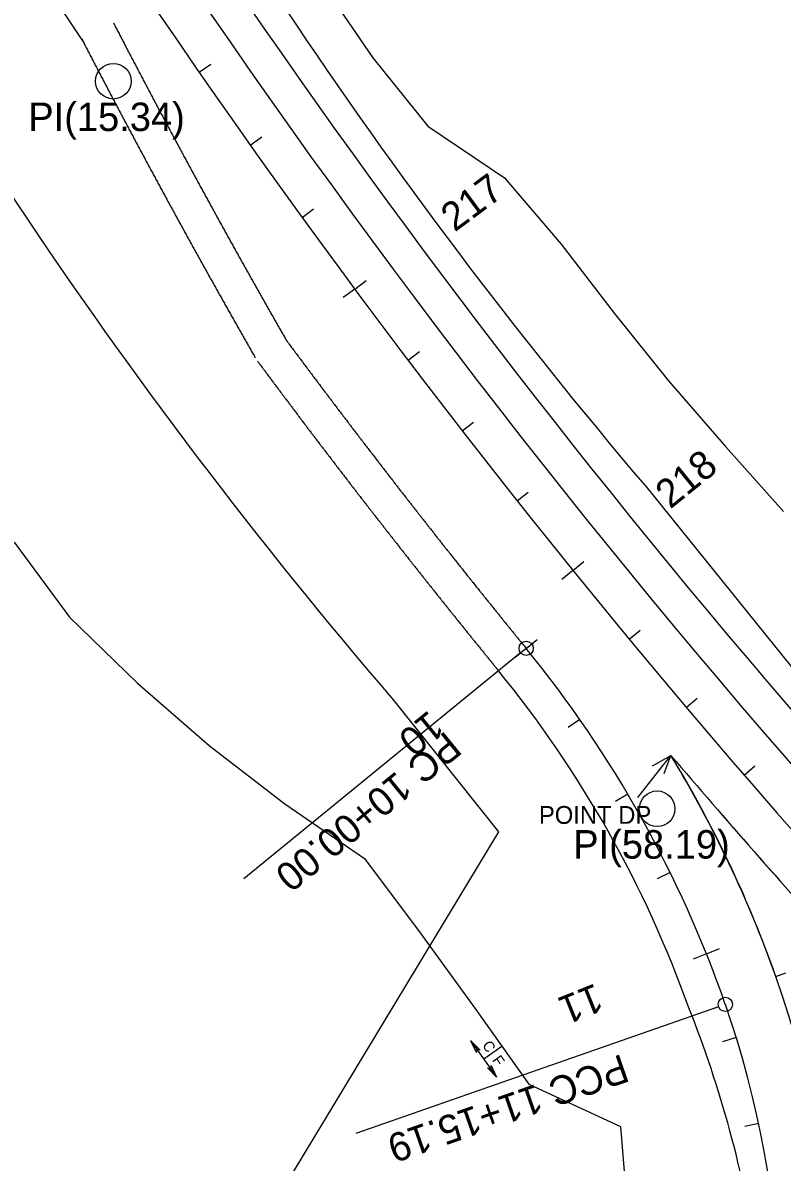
# Model space of a CAD drawing. Extents: x 2717836 to 2719883, y 337327 to 339806.
# Drawn here: x 2718764.3 to 2718977.8, y 338088.2 to 338408.2 of the extents above; entities that cross this region are included whole.
import ezdxf

# ---------------------------------------------------------------- set-up
doc = ezdxf.new("R2010")
doc.units = 0
for name, color, linetype in [('Level 1', 7, 'Continuous'), ('Level 2', 7, 'Continuous'), ('Level 22', 7, 'Continuous'), ('Level 23', 7, 'Continuous'), ('Level 3', 7, 'Continuous'), ('Level 31', 7, 'Continuous'), ('Level 52', 7, 'Continuous'), ('Level 6', 7, 'Continuous'), ('Level 62', 7, 'Continuous'), ('Level 8', 7, 'Continuous')]:
    doc.layers.add(name, color=color, linetype=linetype)

msp = doc.modelspace()

# ---------------------------------------------------------------- linework, layer by layer
at = {"layer": 'Level 1'}
for centre, radius, start, end in [((2720744.45, 339734.24), 2350, 206.79977, 222.16044), ((2718650.19, 338023.77), 330, 19.2398, 39.2398), ((2718697.4, 338040.25), 280, 343.9547, 19.2398)]:
    msp.add_arc(centre, radius, start, end, dxfattribs=at)
at = {"layer": 'Level 2'}
msp.add_arc((2718692.92, 338040.11), 300.27, 344.2175, 19.5026, dxfattribs=at)
at = {"layer": 'Level 22'}
for p, q in [((2718848.86, 338418.64), (2718862.69, 338398.35)), ((2718862.69, 338398.35), (2718878.13, 338379.22)), ((2718878.13, 338379.22), (2718899.73, 338364.7)), ((2718899.73, 338364.7), (2718915.62, 338346.08)), ((2718915.62, 338346.08), (2718930.49, 338326.7)), ((2718930.49, 338326.7), (2718945.81, 338307.67)), ((2718945.81, 338307.67), (2718961.78, 338289.18)), ((2718961.78, 338289.18), (2718978.1, 338271)), ((2718761.89, 338262.37), (2718777.48, 338241.23)), ((2718777.48, 338241.23), (2718796.55, 338222.77)), ((2718796.55, 338222.77), (2718816.65, 338205.23)), ((2718816.65, 338205.23), (2718837.98, 338188.83)), ((2718837.98, 338188.83), (2718860.37, 338173.48)), ((2718860.37, 338173.48), (2718875.97, 338152.58)), ((2718875.97, 338152.58), (2718891.4, 338131.5)), ((2718891.4, 338131.5), (2718898.97, 338120.79)), ((2718898.97, 338120.79), (2718906.54, 338110.09)), ((2718906.54, 338110.09), (2718932.31, 338098.2)), ((2718932.31, 338098.2), (2718934.9, 338066.65))]:
    msp.add_line(p, q, dxfattribs=at)
at = {"layer": 'Level 23'}
for p, q in [((2718939.3, 338278.13), (2718990.26, 338215.01)), ((2718868.5, 338217.98), (2718898.01, 338180.98)), ((2718898.01, 338180.98), (2718493, 337510.9))]:
    msp.add_line(p, q, dxfattribs=at)
for centre, start, end in [((2720030.05, 339206.57), 206.96023, 220.40436), ((2719954.56, 339151.91), 206.65897, 220.69325)]:
    msp.add_arc(centre, 1432.39, start, end, dxfattribs=at)
at = {"layer": 'Level 3'}
msp.add_line((2718975.96, 338140.35), (2718978.77, 338141.36), dxfattribs=at)
for centre, radius, start, end in [((2720744.45, 339734.24), 2338, 206.79977, 222.16044), ((2718650.19, 338023.77), 330, 19.2398, 39.2398), ((2718650.19, 338023.77), 330, 19.2398, 39.2398), ((2718662.07, 338029.42), 332.92, 19.8259, 31.3168), ((2720759.57, 339747.51), 2382.12, 220.43651, 222.14825), ((2718640.38, 338021.68), 355.94, 19.4749, 19.8142), ((2718697.4, 338040.25), 280, 343.9547, 19.2398), ((2718697.4, 338040.25), 280, 343.9547, 19.2398)]:
    msp.add_arc(centre, radius, start, end, dxfattribs=at)
for points in [[(2718789.79, 338408.22), (2718790.1, 338407.61), (2718790.41, 338407.01), (2718790.73, 338406.4), (2718791.04, 338405.79), (2718791.36, 338405.18), (2718791.67, 338404.58), (2718791.99, 338403.97), (2718792.31, 338403.36), (2718792.62, 338402.76), (2718792.94, 338402.15), (2718793.25, 338401.54), (2718793.57, 338400.93), (2718793.88, 338400.33), (2718794.2, 338399.72), (2718794.52, 338399.11), (2718794.84, 338398.51), (2718795.16, 338397.9), (2718795.47, 338397.3), (2718795.79, 338396.69), (2718796.1, 338396.09), (2718796.43, 338395.48), (2718796.74, 338394.88), (2718797.06, 338394.27), (2718797.38, 338393.66), (2718797.7, 338393.06), (2718798.02, 338392.45), (2718798.33, 338391.85), (2718798.66, 338391.24), (2718798.97, 338390.64), (2718799.3, 338390.03), (2718799.62, 338389.42), (2718799.93, 338388.82), (2718800.26, 338388.21), (2718800.57, 338387.61), (2718800.9, 338387), (2718801.21, 338386.4), (2718801.54, 338385.79), (2718801.86, 338385.18), (2718802.18, 338384.58), (2718802.5, 338383.97), (2718802.82, 338383.37), (2718803.15, 338382.77), (2718803.47, 338382.17), (2718803.79, 338381.56), (2718804.12, 338380.95), (2718804.44, 338380.35), (2718804.76, 338379.74), (2718805.08, 338379.14), (2718805.41, 338378.54), (2718805.73, 338377.94), (2718806.05, 338377.33), (2718806.38, 338376.72), (2718806.7, 338376.12), (2718807.03, 338375.52), (2718807.35, 338374.92), (2718807.67, 338374.31), (2718808, 338373.71), (2718808.32, 338373.1), (2718808.64, 338372.51), (2718808.97, 338371.9), (2718809.3, 338371.29), (2718809.62, 338370.69), (2718809.95, 338370.09), (2718810.27, 338369.49), (2718810.6, 338368.88), (2718810.93, 338368.29), (2718811.26, 338367.68), (2718811.58, 338367.07), (2718811.91, 338366.48), (2718812.24, 338365.87), (2718812.56, 338365.27), (2718812.89, 338364.67), (2718813.22, 338364.07), (2718813.55, 338363.46)], [(2718813.55, 338363.46), (2718813.88, 338362.86), (2718814.2, 338362.26), (2718814.53, 338361.65), (2718814.86, 338361.06), (2718815.19, 338360.45), (2718815.52, 338359.85), (2718815.85, 338359.25), (2718816.18, 338358.64), (2718816.51, 338358.05), (2718816.84, 338357.44), (2718817.16, 338356.85), (2718817.5, 338356.24), (2718817.82, 338355.64), (2718818.16, 338355.04), (2718818.49, 338354.44), (2718818.82, 338353.84), (2718819.15, 338353.23), (2718819.48, 338352.64), (2718819.81, 338352.03), (2718820.14, 338351.44), (2718820.48, 338350.83), (2718820.81, 338350.24), (2718821.14, 338349.63), (2718821.48, 338349.03), (2718821.8, 338348.43), (2718822.14, 338347.83), (2718822.47, 338347.24), (2718822.8, 338346.63), (2718823.13, 338346.04), (2718823.47, 338345.43), (2718823.81, 338344.83), (2718824.14, 338344.23), (2718824.47, 338343.63), (2718824.81, 338343.04), (2718825.14, 338342.43), (2718825.47, 338341.84), (2718825.81, 338341.24), (2718826.15, 338340.63), (2718826.48, 338340.04), (2718826.82, 338339.44), (2718827.15, 338338.84), (2718827.49, 338338.24), (2718827.82, 338337.65), (2718828.16, 338337.04), (2718828.5, 338336.44), (2718828.83, 338335.85), (2718829.17, 338335.24), (2718829.5, 338334.65), (2718829.84, 338334.05), (2718830.18, 338333.45), (2718830.52, 338332.85), (2718830.86, 338332.25), (2718831.19, 338331.66), (2718831.53, 338331.06), (2718831.87, 338330.46), (2718832.21, 338329.86), (2718832.54, 338329.27), (2718832.89, 338328.67), (2718833.22, 338328.07), (2718833.56, 338327.47), (2718833.9, 338326.87), (2718834.24, 338326.28), (2718834.58, 338325.68), (2718834.92, 338325.09), (2718835.26, 338324.49), (2718835.6, 338323.89), (2718835.94, 338323.29), (2718836.28, 338322.69), (2718836.62, 338322.1), (2718836.97, 338321.5), (2718837.3, 338320.91), (2718837.65, 338320.31), (2718838.33, 338319.12)], [(2718838.33, 338319.12), (2718838.77, 338318.52), (2718839.22, 338317.92), (2718839.66, 338317.33), (2718840.1, 338316.73), (2718840.54, 338316.14), (2718840.99, 338315.54), (2718841.43, 338314.95), (2718841.87, 338314.36), (2718842.32, 338313.76), (2718842.76, 338313.17), (2718843.21, 338312.57), (2718843.65, 338311.98), (2718844.09, 338311.39), (2718844.54, 338310.79), (2718844.98, 338310.2), (2718845.43, 338309.6), (2718845.87, 338309.01), (2718846.32, 338308.42), (2718846.76, 338307.83), (2718847.21, 338307.24), (2718847.66, 338306.64), (2718848.1, 338306.05), (2718848.55, 338305.45), (2718848.99, 338304.86), (2718849.44, 338304.28), (2718849.89, 338303.68), (2718850.33, 338303.09), (2718850.78, 338302.49), (2718851.23, 338301.91), (2718851.68, 338301.31), (2718852.12, 338300.72), (2718852.57, 338300.13), (2718853.02, 338299.54), (2718853.47, 338298.95), (2718853.92, 338298.36), (2718854.37, 338297.77), (2718854.82, 338297.17), (2718855.26, 338296.59), (2718855.71, 338296), (2718856.16, 338295.4), (2718856.61, 338294.82), (2718857.06, 338294.22), (2718857.51, 338293.64), (2718857.96, 338293.05), (2718858.41, 338292.46), (2718858.86, 338291.87), (2718859.32, 338291.28), (2718859.76, 338290.69), (2718860.22, 338290.1), (2718860.67, 338289.51), (2718861.12, 338288.93), (2718861.57, 338288.34), (2718862.02, 338287.75), (2718862.48, 338287.16), (2718862.93, 338286.57), (2718863.38, 338285.99), (2718863.83, 338285.4), (2718864.28, 338284.81), (2718864.74, 338284.22), (2718865.19, 338283.64), (2718865.65, 338283.05), (2718866.1, 338282.46), (2718866.55, 338281.88), (2718867.01, 338281.29), (2718867.46, 338280.7), (2718867.91, 338280.11), (2718868.37, 338279.53), (2718868.82, 338278.95), (2718869.28, 338278.36), (2718869.73, 338277.77), (2718870.19, 338277.18), (2718870.64, 338276.6), (2718871.1, 338276.01), (2718871.55, 338275.43)], [(2718871.55, 338275.43), (2718872.01, 338274.85), (2718872.47, 338274.26), (2718872.92, 338273.68), (2718873.38, 338273.09), (2718873.83, 338272.51), (2718874.29, 338271.92), (2718874.75, 338271.34), (2718875.2, 338270.76), (2718875.66, 338270.17), (2718876.12, 338269.59), (2718876.58, 338269), (2718877.03, 338268.42), (2718877.49, 338267.84), (2718877.95, 338267.25), (2718878.41, 338266.67), (2718878.87, 338266.08), (2718879.33, 338265.5), (2718879.79, 338264.92), (2718880.25, 338264.34), (2718880.7, 338263.76), (2718881.17, 338263.17), (2718881.62, 338262.59), (2718882.09, 338262.01), (2718882.54, 338261.43), (2718883, 338260.85), (2718883.46, 338260.26), (2718883.92, 338259.69), (2718884.39, 338259.1), (2718884.85, 338258.52), (2718885.31, 338257.94), (2718885.77, 338257.36), (2718886.23, 338256.78), (2718886.69, 338256.2), (2718887.15, 338255.62), (2718887.62, 338255.04), (2718888.08, 338254.46), (2718888.54, 338253.88), (2718889, 338253.3), (2718889.46, 338252.72), (2718889.93, 338252.14), (2718890.39, 338251.56), (2718890.86, 338250.98), (2718891.32, 338250.4), (2718891.78, 338249.83), (2718892.25, 338249.24), (2718892.71, 338248.67), (2718893.18, 338248.08), (2718893.64, 338247.51), (2718894.11, 338246.93), (2718894.57, 338246.35), (2718895.03, 338245.78), (2718895.5, 338245.2), (2718895.96, 338244.62), (2718896.43, 338244.04), (2718896.89, 338243.46), (2718897.36, 338242.89), (2718897.83, 338242.31), (2718898.29, 338241.74), (2718898.76, 338241.15), (2718899.22, 338240.58), (2718899.7, 338240), (2718900.16, 338239.43), (2718900.62, 338238.85), (2718901.09, 338238.27), (2718901.56, 338237.7), (2718902.03, 338237.12), (2718902.5, 338236.55), (2718902.96, 338235.98), (2718903.43, 338235.4), (2718903.9, 338234.83), (2718904.37, 338234.25), (2718904.84, 338233.67), (2718905.78, 338232.52)]]:
    msp.add_spline(points, degree=3, dxfattribs=at)
at = {"layer": 'Level 31'}
for p, q in [((2718813.86, 338394.34), (2718817.15, 338396.62)), ((2718828.22, 338373.88), (2718831.49, 338376.2)), ((2718842.8, 338353.57), (2718846.04, 338355.92)), ((2718857.6, 338333.42), (2718860.81, 338335.81)), ((2718857.6, 338333.42), (2718854.39, 338331.04)), ((2718872.61, 338313.43), (2718875.79, 338315.85)), ((2718887.83, 338293.6), (2718890.99, 338296.05)), ((2718903.26, 338273.93), (2718906.39, 338276.41)), ((2718918.9, 338254.42), (2718922.01, 338256.94)), ((2718918.9, 338254.42), (2718915.79, 338251.9)), ((2718934.74, 338235.09), (2718937.82, 338237.64)), ((2718905.78, 338232.52), (2718908.88, 338235.05)), ((2718904.23, 338231.26), (2718826.46, 338167.74)), ((2718905.78, 338232.52), (2718902.68, 338229.99)), ((2718950.8, 338215.92), (2718953.85, 338218.5)), ((2718920.84, 338212.58), (2718917.56, 338210.29)), ((2718967.05, 338196.92), (2718970.07, 338199.54)), ((2718934.36, 338191.55), (2718930.91, 338189.52)), ((2718946.24, 338169.56), (2718942.65, 338167.8)), ((2718956.43, 338146.74), (2718952.71, 338145.25)), ((2718956.43, 338146.74), (2718960.14, 338148.23)), ((2718959.87, 338131.86), (2718857.93, 338096.28)), ((2718964.83, 338123.2), (2718961.01, 338122.02)), ((2718971.16, 338099.03), (2718967.25, 338098.19))]:
    msp.add_line(p, q, dxfattribs=at)
for centre, radius in [((2718789.76, 338391.81), 5), ((2718905.78, 338232.52), 2), ((2718942.59, 338187.46), 5), ((2718961.76, 338132.52), 2)]:
    msp.add_circle(centre, radius, dxfattribs=at)
at = {"layer": 'Level 52'}
for p, q in [((2718890.26, 338122.28), (2718897.48, 338112.08)), ((2718893.87, 338117.18), (2718898.97, 338120.79))]:
    msp.add_line(p, q, dxfattribs=at)
for points in [[(2718890.26, 338122.28), (2718892.83, 338119.69), (2718891.81, 338120.08), (2718891.83, 338118.98)], [(2718897.48, 338112.08), (2718894.9, 338114.67), (2718895.92, 338114.29), (2718895.91, 338115.38)]]:
    msp.add_lwpolyline(points, close=True, dxfattribs=at)
at = {"layer": 'Level 6'}
for centre, radius, start, end in [((2720744.45, 339734.24), 2372, 206.79977, 214.15238), ((2720744.45, 339734.24), 2328, 208.64257, 222.16044), ((2718650.19, 338023.77), 320, 19.6898, 39.2398), ((2718654.26, 338013.03), 320, 8.6881, 21.747)]:
    msp.add_arc(centre, radius, start, end, dxfattribs=at)
for points in [[(2718780.91, 338403.62), (2718781.22, 338403.02), (2718781.53, 338402.41), (2718781.85, 338401.8), (2718782.17, 338401.19), (2718782.48, 338400.58), (2718782.8, 338399.97), (2718783.12, 338399.35), (2718783.44, 338398.75), (2718783.75, 338398.14), (2718784.07, 338397.53), (2718784.38, 338396.92), (2718784.7, 338396.31), (2718785.02, 338395.71), (2718785.34, 338395.09), (2718785.66, 338394.48), (2718785.97, 338393.88), (2718786.29, 338393.26), (2718786.61, 338392.66), (2718786.93, 338392.05), (2718787.25, 338391.44), (2718787.57, 338390.83), (2718787.89, 338390.23), (2718788.21, 338389.61), (2718788.53, 338389), (2718788.85, 338388.4), (2718789.17, 338387.79), (2718789.49, 338387.18), (2718789.81, 338386.57), (2718790.13, 338385.97), (2718790.46, 338385.35), (2718790.78, 338384.75), (2718791.09, 338384.14), (2718791.42, 338383.53), (2718791.74, 338382.93), (2718792.06, 338382.32), (2718792.38, 338381.72), (2718792.71, 338381.1), (2718793.03, 338380.49), (2718793.35, 338379.89), (2718793.68, 338379.28), (2718794, 338378.68), (2718794.32, 338378.07), (2718794.64, 338377.46), (2718794.97, 338376.85), (2718795.29, 338376.24), (2718795.61, 338375.64), (2718795.94, 338375.03), (2718796.26, 338374.43), (2718796.59, 338373.82), (2718796.91, 338373.22), (2718797.24, 338372.6), (2718797.57, 338372), (2718797.89, 338371.4), (2718798.22, 338370.79), (2718798.54, 338370.18), (2718798.87, 338369.57), (2718799.19, 338368.97), (2718799.52, 338368.36), (2718799.84, 338367.76), (2718800.18, 338367.15), (2718800.5, 338366.54), (2718800.82, 338365.94), (2718801.15, 338365.33), (2718801.48, 338364.73), (2718801.81, 338364.12), (2718802.13, 338363.52), (2718802.47, 338362.91), (2718802.79, 338362.3), (2718803.12, 338361.71), (2718803.45, 338361.1), (2718803.78, 338360.5), (2718804.11, 338359.89), (2718804.43, 338359.29), (2718804.77, 338358.67)], [(2718804.77, 338358.67), (2718805.1, 338358.07), (2718805.42, 338357.47), (2718805.76, 338356.86), (2718806.08, 338356.26), (2718806.42, 338355.66), (2718806.74, 338355.06), (2718807.08, 338354.44), (2718807.41, 338353.84), (2718807.74, 338353.24), (2718808.07, 338352.63), (2718808.4, 338352.04), (2718808.73, 338351.43), (2718809.06, 338350.83), (2718809.4, 338350.21), (2718809.73, 338349.61), (2718810.06, 338349.02), (2718810.39, 338348.41), (2718810.72, 338347.81), (2718811.06, 338347.2), (2718811.39, 338346.6), (2718811.72, 338346), (2718812.05, 338345.4), (2718812.4, 338344.79), (2718812.73, 338344.19), (2718813.06, 338343.59), (2718813.39, 338342.98), (2718813.73, 338342.38), (2718814.06, 338341.78), (2718814.39, 338341.18), (2718814.73, 338340.57), (2718815.07, 338339.97), (2718815.4, 338339.37), (2718815.74, 338338.77), (2718816.07, 338338.17), (2718816.41, 338337.56), (2718816.74, 338336.96), (2718817.08, 338336.35), (2718817.42, 338335.75), (2718817.75, 338335.16), (2718818.09, 338334.55), (2718818.43, 338333.95), (2718818.77, 338333.35), (2718819.1, 338332.75), (2718819.44, 338332.14), (2718819.78, 338331.54), (2718820.12, 338330.95), (2718820.46, 338330.34), (2718820.79, 338329.74), (2718821.13, 338329.14), (2718821.47, 338328.54), (2718821.81, 338327.93), (2718822.15, 338327.34), (2718822.49, 338326.74), (2718822.83, 338326.14), (2718823.16, 338325.54), (2718823.51, 338324.94), (2718823.84, 338324.34), (2718824.19, 338323.74), (2718824.52, 338323.14), (2718824.87, 338322.53), (2718825.21, 338321.93), (2718825.55, 338321.34), (2718825.89, 338320.74), (2718826.23, 338320.14), (2718826.57, 338319.54), (2718826.91, 338318.94), (2718827.26, 338318.33), (2718827.6, 338317.74), (2718827.94, 338317.14), (2718828.28, 338316.54), (2718828.62, 338315.94), (2718828.97, 338315.34), (2718829.65, 338314.15)], [(2718830.3, 338313.15), (2718830.74, 338312.56), (2718831.19, 338311.96), (2718831.63, 338311.36), (2718832.08, 338310.76), (2718832.52, 338310.17), (2718832.97, 338309.57), (2718833.41, 338308.97), (2718833.86, 338308.38), (2718834.31, 338307.78), (2718834.75, 338307.18), (2718835.2, 338306.58), (2718835.64, 338305.99), (2718836.08, 338305.4), (2718836.54, 338304.79), (2718836.98, 338304.2), (2718837.43, 338303.6), (2718837.87, 338303.01), (2718838.33, 338302.41), (2718838.77, 338301.82), (2718839.21, 338301.23), (2718839.67, 338300.63), (2718840.11, 338300.03), (2718840.56, 338299.43), (2718841.01, 338298.84), (2718841.46, 338298.25), (2718841.91, 338297.65), (2718842.35, 338297.06), (2718842.81, 338296.46), (2718843.25, 338295.87), (2718843.71, 338295.27), (2718844.15, 338294.68), (2718844.6, 338294.09), (2718845.05, 338293.49), (2718845.5, 338292.91), (2718845.96, 338292.31), (2718846.4, 338291.72), (2718846.86, 338291.12), (2718847.31, 338290.53), (2718847.75, 338289.94), (2718848.21, 338289.34), (2718848.66, 338288.76), (2718849.11, 338288.16), (2718849.56, 338287.57), (2718850.01, 338286.98), (2718850.47, 338286.38), (2718850.92, 338285.8), (2718851.38, 338285.2), (2718851.83, 338284.61), (2718852.28, 338284.02), (2718852.73, 338283.43), (2718853.18, 338282.84), (2718853.64, 338282.24), (2718854.09, 338281.66), (2718854.55, 338281.06), (2718855, 338280.48), (2718855.45, 338279.89), (2718855.91, 338279.29), (2718856.36, 338278.71), (2718856.82, 338278.11), (2718857.27, 338277.53), (2718857.73, 338276.93), (2718858.19, 338276.35), (2718858.64, 338275.76), (2718859.1, 338275.17), (2718859.55, 338274.58), (2718860.01, 338273.99), (2718860.46, 338273.4), (2718860.92, 338272.82), (2718861.38, 338272.22), (2718861.83, 338271.64), (2718862.29, 338271.05), (2718862.75, 338270.46), (2718863.21, 338269.87), (2718863.66, 338269.29)], [(2718863.66, 338269.28), (2718864.12, 338268.7), (2718864.58, 338268.11), (2718865.04, 338267.53), (2718865.5, 338266.93), (2718865.95, 338266.35), (2718866.42, 338265.76), (2718866.87, 338265.17), (2718867.33, 338264.59), (2718867.79, 338264), (2718868.25, 338263.42), (2718868.71, 338262.83), (2718869.17, 338262.24), (2718869.63, 338261.66), (2718870.09, 338261.07), (2718870.55, 338260.49), (2718871.01, 338259.9), (2718871.47, 338259.32), (2718871.93, 338258.73), (2718872.39, 338258.15), (2718872.85, 338257.57), (2718873.32, 338256.98), (2718873.77, 338256.39), (2718874.24, 338255.8), (2718874.7, 338255.22), (2718875.16, 338254.64), (2718875.63, 338254.05), (2718876.09, 338253.48), (2718876.55, 338252.89), (2718877.01, 338252.31), (2718877.48, 338251.72), (2718877.94, 338251.14), (2718878.4, 338250.56), (2718878.87, 338249.97), (2718879.33, 338249.39), (2718879.8, 338248.8), (2718880.26, 338248.23), (2718880.72, 338247.65), (2718881.19, 338247.06), (2718881.65, 338246.48), (2718882.12, 338245.89), (2718882.58, 338245.32), (2718883.05, 338244.73), (2718883.51, 338244.15), (2718883.98, 338243.57), (2718884.44, 338242.99), (2718884.91, 338242.41), (2718885.38, 338241.82), (2718885.84, 338241.25), (2718886.31, 338240.66), (2718886.78, 338240.09), (2718887.24, 338239.51), (2718887.71, 338238.92), (2718888.18, 338238.35), (2718888.65, 338237.76), (2718889.11, 338237.18), (2718889.58, 338236.61), (2718890.05, 338236.03), (2718890.51, 338235.45), (2718890.99, 338234.86), (2718891.45, 338234.29), (2718891.93, 338233.71), (2718892.39, 338233.13), (2718892.86, 338232.56), (2718893.33, 338231.97), (2718893.8, 338231.4), (2718894.27, 338230.82), (2718894.74, 338230.24), (2718895.21, 338229.67), (2718895.68, 338229.08), (2718896.15, 338228.51), (2718896.62, 338227.93), (2718897.09, 338227.35), (2718898.03, 338226.2)]]:
    msp.add_spline(points, degree=3, dxfattribs=at)
at = {"layer": 'Level 62'}
for p in [(2718937.16, 338190.61), (2718941.32, 338199.49), (2718944.58, 338197.32)]:
    msp.add_line(p, (2718946.48, 338202.46), dxfattribs=at)
at = {"layer": 'Level 8'}
msp.add_line((2718975.96, 338140.35), (2718978.77, 338141.36), dxfattribs=at)
for centre, radius, start, end in [((2720744.45, 339734.24), 2362, 220.42917, 222.16044), ((2718650.19, 338023.78), 346, 19.6893, 31.0937)]:
    msp.add_arc(centre, radius, start, end, dxfattribs=at)

# ---------------------------------------------------------------- texts
at = {"layer": 'Level 31'}
for s, p in [('PI(15.34)', (2718765.85, 338377.81)), ('PI(58.19)', (2718919, 338173.46))]:
    msp.add_text(s, height=8, dxfattribs=at).set_placement(p)
for s, rotation, p in [('217', 36.5905, (2718885.68, 338349.29)), ('218', 39.0286, (2718946.28, 338271.47)), ('10', 219.2398, (2718878.46, 338215.38)), ('PC 10+00.00', 219.2398, (2718883.21, 338209.57)), ('11', 201.8775, (2718925.24, 338138.53)), ('PCC 11+15.19', 199.2398, (2718932.7, 338118.67))]:
    msp.add_text(s, height=8, rotation=rotation, dxfattribs=at).set_placement(p)
at = {"layer": 'Level 52'}
for s, p in [('C', (2718893.28, 338121.02)), ('F', (2718896.09, 338116.85))]:
    msp.add_text(s, height=3, rotation=305.2872, dxfattribs=at).set_placement(p)
at = {"layer": 'Level 62'}
msp.add_text('POINT DP', height=5, dxfattribs=at).set_placement((2718909.37, 338183.23))

doc.saveas('drawing.dxf')
